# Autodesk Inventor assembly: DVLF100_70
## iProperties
Created: 2010-03
Part Number: DVLF100_70
Document SubType Name: Assembly
Designer: TB
Mass: 3585.86 g
Surface Area: 3779.27 cm^2
Volume: 3585.86 cm^3
Density: 1 g/cm^3
Description: KM DVLF 100/70 - 100 mm
Slaglengde: 100.000 mm
Author: TB
